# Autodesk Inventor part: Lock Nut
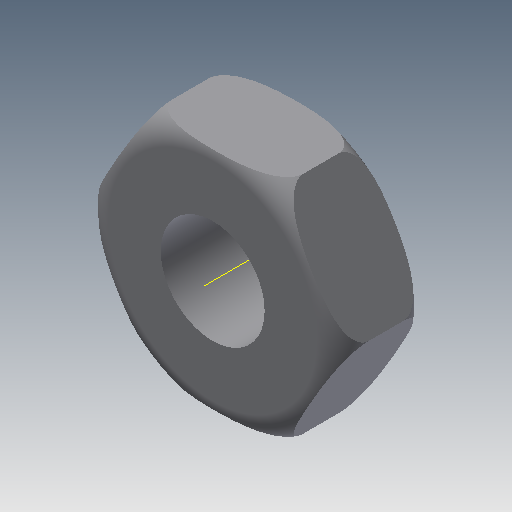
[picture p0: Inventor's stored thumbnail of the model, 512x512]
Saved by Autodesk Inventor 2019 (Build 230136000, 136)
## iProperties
Created: 2009-04
Part Number: Lock Nut
Document SubType Name: Modeling
Designer: Sham
Density: 1 g/cm^3
Material: Generic
Appearance: Default
Author: Sham
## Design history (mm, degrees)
sketch "Sketch1"
  geometry: L1 (7.5, 12.99)-(15, 0); L2 (15, 0)-(7.5, -12.99); L3 (7.5, -12.99)-(-7.5, -12.99); L4 (-7.5, -12.99)-(-15, 0); L5 (-15, 0)-(-7.5, 12.99); L6 (-7.5, 12.99)-(7.5, 12.99); C1 r 6 at (0, 0); 1 further point
  constraints: 12 end point, 1 centre point, 1 coincident, 13 other
  dimensions: "d0" = 30 distance of L1.end L4.end; "d1" = 12 diameter of C1
extrude "Extrusion1" new body sketch "Sketch1" distance "d2" = 10; taper "d3" = 0 deg
sketch "Sketch2"
  geometry: L1 (-12, 0)-(-12, -0.022); L2 (-15, 7)-(-15, 3); L3 (0, -2.87)-(0, 12.87) reference; A1 r 3 centre (-12, 7) between (-12, 10) and (-15, 7); A2 r 3 centre (-12, 3) between (-15, 3) and (-12, 0)
  constraints: 4 end point, 4 point on circle, 2 centre point, 1 tangent
revolve "Revolution1" sketch "Sketch2" stored, may be unused: angle "d7" = 90 deg
body "Solid1"
other parameters: "d6" = 90 deg
